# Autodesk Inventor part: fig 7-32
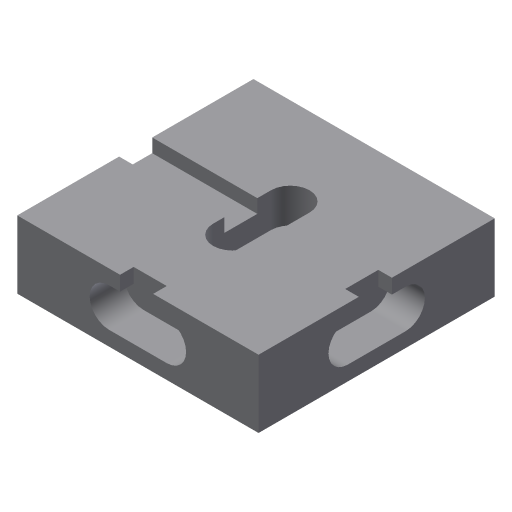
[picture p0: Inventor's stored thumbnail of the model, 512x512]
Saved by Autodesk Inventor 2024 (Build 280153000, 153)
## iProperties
Created: 2004-05
Part Number: fig 7-32
Document SubType Name: Modeling
Designer: CADCIM Technologies
Manufacturer: Standard
Standards Organization: Custom
Density: 1 g/cm^3
Material: Generic
Appearance: Default
Author: CADCIM Technologies
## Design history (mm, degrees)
sketch "Sketch1"
  geometry: L1 (-30.233, -25.517)-(22.302, -25.517); L2 (22.302, -25.517)-(22.302, 25.904); L3 (22.302, 25.904)-(-30.233, 25.904); L4 (-30.233, 25.904)-(-30.233, -25.517)
  constraints: 8 end point, 2 parallel, 1 horizontal, 1 perpendicular
extrude "Extrusion1" new body sketch "Sketch1" distance "d0" = 14.75; taper "d1" = 0 deg
sketch "Sketch2"
  geometry: L1 (1.047, -5.75)-(1.047, 6.846); L2 (-7.35, 6.845)-(-7.35, -5.75); A1 r 4.198 centre (-3.152, 6.846) between (1.047, 6.846) and (-7.35, 6.845); A2 r 4.198 centre (-3.152, -5.75) between (-7.35, -5.75) and (1.047, -5.75)
  constraints: 4 end point, 4 point on circle, 4 tangent, 2 centre point, 1 parallel
extrude "Extrusion2" cut sketch "Sketch2" distance "d2" = 7.5; taper "d3" = 0 deg
sketch "Sketch3"
  geometry: L1 (-7.5, 0)-(-7.5, 12.595) reference; L2 (-7.5, 0)-(0, 0) reference; L3 (-7.5, 2.416)-(-4.537, 2.416); L4 (-4.537, 2.416)-(-4.537, 9.616); L5 (-4.537, 9.616)-(-7.5, 9.616)
  constraints: 6 end point, 2 perpendicular, 2 point on line, 1 parallel
extrude "Extrusion3" cut sketch "Sketch3" extent not by distance; stored distance "d4" = 6.75; taper "d5" = 0 deg
sketch "Sketch4"
  geometry: L1 (1.047, -5.75)-(1.047, 6.846); L2 (-7.35, 6.845)-(-7.35, -5.75); A1 r 4.198 centre (-3.152, 6.846) between (1.047, 6.846) and (-7.35, 6.845); A2 r 4.198 centre (-3.152, -5.75) between (-7.35, -5.75) and (1.047, -5.75)
  constraints: 4 end point, 4 point on circle, 4 tangent, 2 centre point, 1 parallel
extrude "Extrusion4" cut sketch "Sketch4" taper "d7" = 0 deg; distance "d8" = 7.5
sketch "Sketch5"
  geometry: L1 (-7.5, 0)-(-7.5, 12.595) reference; L2 (-7.5, 0)-(0, 0) reference; L3 (-7.5, 2.416)-(-4.537, 2.416); L4 (-4.537, 2.416)-(-4.537, 9.616); L5 (-4.537, 9.616)-(-7.5, 9.616)
  constraints: 6 end point, 2 perpendicular, 2 point on line, 1 parallel
extrude "Extrusion5" cut sketch "Sketch5" extent not by distance; taper "d10" = 0 deg; stored distance "d11" = 6.75
sketch "Sketch6"
  geometry: L1 (1.047, -5.75)-(1.047, 6.846); L2 (-7.35, 6.845)-(-7.35, -5.75); A1 r 4.198 centre (-3.152, 6.846) between (1.047, 6.846) and (-7.35, 6.845); A2 r 4.198 centre (-3.152, -5.75) between (-7.35, -5.75) and (1.047, -5.75)
  constraints: 4 end point, 4 point on circle, 4 tangent, 2 centre point, 1 parallel
extrude "Extrusion6" cut sketch "Sketch6" taper "d13" = 0 deg; distance "d14" = 7.5
sketch "Sketch7"
  geometry: L1 (-7.5, 0)-(-7.5, 12.595) reference; L2 (-7.5, 0)-(0, 0) reference; L3 (-7.5, 2.416)-(-4.537, 2.416); L4 (-4.537, 2.416)-(-4.537, 9.616); L5 (-4.537, 9.616)-(-7.5, 9.616)
  constraints: 6 end point, 2 perpendicular, 2 point on line, 1 parallel
extrude "Extrusion7" cut sketch "Sketch7" extent not by distance; taper "d16" = 0 deg; stored distance "d17" = 6.75
body "Solid1"
